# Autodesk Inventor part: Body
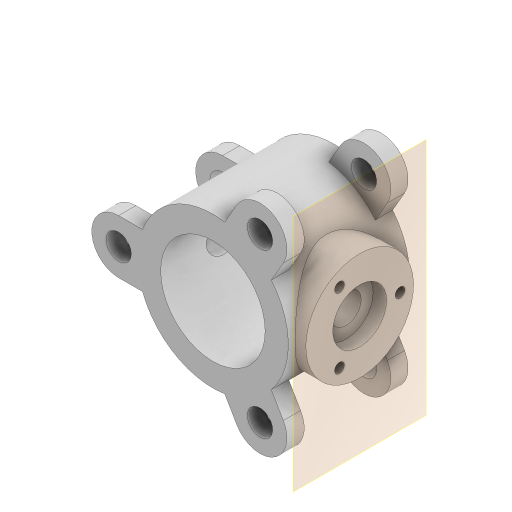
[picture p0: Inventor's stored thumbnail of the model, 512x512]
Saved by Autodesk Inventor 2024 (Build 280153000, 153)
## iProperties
Created: 2019-03
Part Number: Body
Material: Generic
Document SubType Name: Modeling
Designer: LENOVO-CADCIM
Density: 1 g/cm^3
Appearance: Default
Author: LENOVO-CADCIM
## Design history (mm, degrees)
sketch "Sketch1"
  geometry: C1 r 140 at (0, 0); C2 r 97 at (0, 0); 1 further point
  constraints: 2 centre point, 2 coincident
  dimensions: "d0" = 194 diameter of C2; "d1" = 280 diameter of C1
extrude "Extrusion1" new body sketch "Sketch1" stored distance "d2" = 225; taper "d3" = 0 deg
sketch "Sketch2"
  geometry: L1 (0, 0)-(-428, 0); L2 (-130.767, 50)-(-175, 50); L3 (-130.767, -50)-(-175, -50); C1 r 23.5 at (-175, 0); A1 r 175 centre (0, 0) between (-175, 0) and (-175, 0); A2 r 140 centre (0, 0) between (-130.767, 50) and (-130.767, -50) reference; A3 r 50 centre (-175, 0) between (-175, 50) and (-175, -50); 1 further point
  constraints: 6 end point, 6 point on circle, 3 centre point, 3 horizontal, 2 tangent, 1 coincident, 1 point on line, 1 other
  dimensions: "d4" = 350 diameter of A1; "d5" = 50 radius of A3; "d6" = 47 diameter of C1
extrude "Extrusion2" join sketch "Sketch2" distance "d7" = 32; taper "d8" = 0 deg
pattern_circular "Circular Pattern1" dims angle "d10" = 360 deg
mirror "Mirror1"
workplane "Work Plane1"
sketch "Sketch3"
  geometry: C1 r 100 at (0, 0); 1 further point
  constraints: 1 centre point, 1 coincident
  dimensions: "d13" = 200 diameter of C1
extrude "Extrusion3" join sketch "Sketch3" stored distance "d14" = 32; taper "d15" = 0 deg
sketch "Sketch4" dims "d16" = 150
  geometry: L1 (0, 0)-(102, 0); 2 further points
  constraints: 2 end point, 1 coincident, 1 horizontal, 1 horizontal alignment, 1 point on line, 2 other
hole "Hole1" sketch "Sketch4" at (75, 0) diameter "d17" = 18.376; stored, may be unused: countersink angle "d21" = 90 deg, drill point angle "d23" = 118 deg; dims "d18" = 40, "d19" = 4, "d20" = 2, "d22" = 47.3
pattern_circular "Circular Pattern2" dims angle "d25" = 360 deg
sketch "Sketch5"
  geometry: C1 r 100 at (0, 0) reference; 2 further points
  constraints: 1 coincident
hole "Hole2" sketch "Sketch5" diameter "d27" = 56; stored, may be unused: countersink angle "d31" = 90 deg, drill point angle "d33" = 118 deg; dims "d28" = 6, "d29" = 100, "d30" = 25, "d32" = 310
body "Solid1"
